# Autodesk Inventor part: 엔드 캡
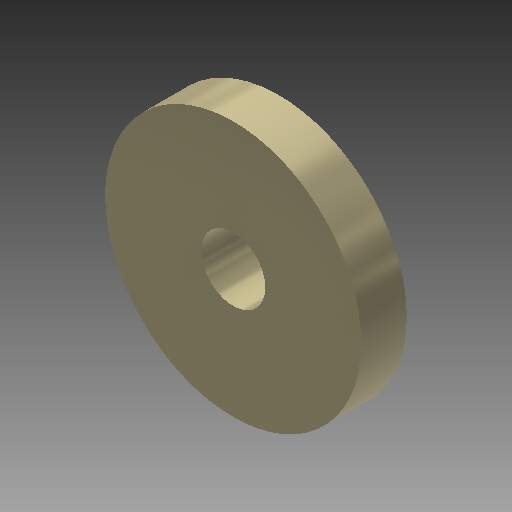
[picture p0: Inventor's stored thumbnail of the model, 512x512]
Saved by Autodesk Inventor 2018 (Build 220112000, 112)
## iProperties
Created: 2024-01
Part Number: 엔드 캡
Material: 강철, 연강
Document SubType Name: Modeling
Designer: mdu-01
Density: 1 g/cm^3
Appearance: 강철(1)
Author: mdu-01
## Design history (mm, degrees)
sketch "스케치1"
  geometry: C1 r 9 at (0, 0); 1 further point
  constraints: 1 centre point, 1 coincident
  dimensions: "d0" = 18 diameter of C1
extrude "돌출1" new body sketch "스케치1" distance "d1" = 3.2; taper "d2" = 0 deg
hole "구멍1" diameter "d5" = 4.5; stored, may be unused: countersink angle "d9" = 90 deg, drill point angle "d11" = 118 deg; dims "d3" = 10, "d4" = 10, "d6" = 6, "d7" = 9.4, "d8" = 2, "d10" = 8
node "솔리드1"
